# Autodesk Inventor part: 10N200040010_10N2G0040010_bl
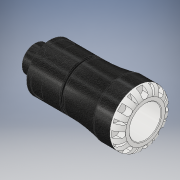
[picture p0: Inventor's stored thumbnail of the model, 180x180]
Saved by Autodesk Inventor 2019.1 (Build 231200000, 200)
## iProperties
Created: 2016-12
Part Number: 10N200040010_10N2G0040010_bl
Material: PVC-Piping
Description: PLASSON MALE ADAPTOR 40X1" SERIES 1
Document SubType Name: Modeling
Designer: KIM
Mass: 61.7504 g
Surface Area: 140.097 cm^2
Volume: 44.1074 cm^3
Density: 1.4 g/cm^3
Appearance: Black Cast
Author: KIM
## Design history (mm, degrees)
derived "10N20.ipt"
feature "Solid1::10N20.ipt" dims "ScaleForDerivedMember" = 10
tag "TaggingFeature1"
body "Solid1"
other parameters: "d1" = 30.66 [user parameter], "d6" = 73 [user parameter], "d8" = 59.5 [user parameter], "d13" = 8 [user parameter], "d14" = 8 [user parameter], "d15" = 0 [user parameter], "d17" = 360 deg [user parameter], "d19" = 8 deg [user parameter], "d20" = 0.8 [user parameter], "d21" = 0.8 [user parameter], "d22" = 8 deg [user parameter], "d24" = 0 [user parameter], "d26" = 360 deg [user parameter], "d32" = 0.925 [user parameter], "d33" = 7 [user parameter], "d34" = 33.249 [user parameter], "d35" = 8 [user parameter], "d38" = 19 [user parameter], "d39" = 0.99747 [user parameter], "d42" = 14 [user parameter], "d43" = 9.2 [user parameter], "d45" = 15.68 [user parameter], "d46" = 0 [user parameter], "d59" = 360 deg [user parameter], "d61" = 11.9 [user parameter], "d62" = 0.8 [user parameter], "d64" = 0 [user parameter], "d65" = 0.7 [user parameter], "d69" = 2 [user parameter], "d70" = 2.1 [user parameter], "d71" = 3 [user parameter], "d73" = 1 [user parameter], "l_" = 73 [user parameter], "R_" = 33.249 [user parameter], "l_2" = 19 [user parameter]
